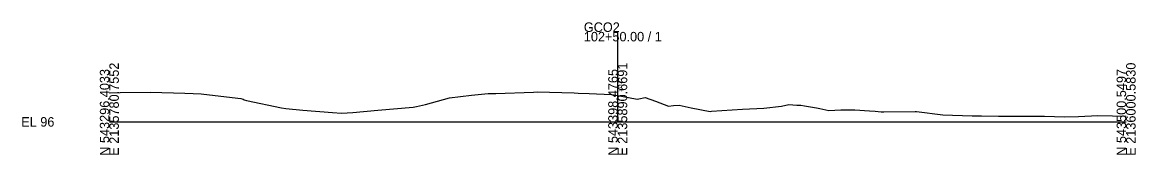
# Model space of a CAD drawing. Extents: x -14327 to 8886, y -10 to 39048.
# Drawn here: x 3974.3 to 4302.8, y 24990.3 to 25029.4 of the extents above; entities that cross this region are included whole.
import ezdxf

# ---------------------------------------------------------------- set-up
doc = ezdxf.new("R2010")
doc.units = 0
for name, color, linetype in [('RD_GPK_XS_Cell', 7, 'Continuous'), ('RD_XS_ExGround', 7, 'Continuous'), ('RD_XS_TX_Elev_EX', 7, 'Continuous')]:
    doc.layers.add(name, color=color, linetype=linetype)

msp = doc.modelspace()

# ---------------------------------------------------------------- linework, layer by layer
at = {"layer": 'RD_GPK_XS_Cell'}
for p, q in [((4150, 25000), (4150, 25026.55)), ((4000, 25000), (4150, 25000)), ((4150, 25000), (4300, 25000))]:
    msp.add_line(p, q, dxfattribs=at)
at = {"layer": 'RD_XS_ExGround'}
for p, q in [((4000, 25008.57), (4000.22, 25008.58)), ((4000.22, 25008.58), (4003.21, 25008.64)), ((4003.21, 25008.64), (4012.16, 25008.8)), ((4012.16, 25008.8), (4022.28, 25008.49)), ((4022.28, 25008.49), (4024.75, 25008.41)), ((4024.75, 25008.41), (4027.09, 25008.3)), ((4027.09, 25008.3), (4027.83, 25008.2)), ((4027.83, 25008.2), (4038.78, 25006.88)), ((4106.81, 25007.88), (4111.73, 25008.36)), ((4111.73, 25008.36), (4112.85, 25008.39)), ((4112.85, 25008.39), (4114.02, 25008.42)), ((4114.02, 25008.42), (4125.1, 25008.81)), ((4125.1, 25008.81), (4126.25, 25008.85)), ((4126.25, 25008.85), (4137.16, 25008.55)), ((4137.16, 25008.55), (4138.33, 25008.51)), ((4138.33, 25008.51), (4141.61, 25008.39)), ((4141.61, 25008.39), (4148.2, 25008.11)), ((4148.2, 25008.11), (4150, 25007.77)), ((4038.78, 25006.88), (4039.45, 25006.68)), ((4039.45, 25006.68), (4039.81, 25006.52)), ((4039.81, 25006.52), (4040.45, 25006.29)), ((4040.45, 25006.29), (4050.84, 25004.18)), ((4090.59, 25004.54), (4091.53, 25004.78)), ((4091.53, 25004.78), (4093.33, 25005.13)), ((4093.33, 25005.13), (4100.33, 25007.07)), ((4100.33, 25007.07), (4106.81, 25007.88)), ((4150, 25007.77), (4155.24, 25006.8)), ((4155.24, 25006.8), (4155.77, 25006.69)), ((4155.77, 25006.69), (4156.26, 25006.8)), ((4156.26, 25006.8), (4158.13, 25007.23)), ((4158.13, 25007.23), (4161.14, 25006.08)), ((4161.14, 25006.08), (4165.02, 25004.66)), ((4165.02, 25004.66), (4166.46, 25004.8)), ((4166.46, 25004.8), (4168.13, 25004.89)), ((4168.13, 25004.89), (4171.68, 25004.18)), ((4193.07, 25004.01), (4198.3, 25004.64)), ((4198.3, 25004.64), (4200.44, 25005.1)), ((4200.44, 25005.1), (4202.81, 25004.93)), ((4202.81, 25004.93), (4204.01, 25004.9)), ((4204.01, 25004.9), (4205.06, 25004.73)), ((4205.06, 25004.73), (4208.69, 25004.17)), ((4050.84, 25004.18), (4052.07, 25003.95)), ((4052.07, 25003.95), (4057.1, 25003.49)), ((4057.1, 25003.49), (4065.8, 25002.76)), ((4065.8, 25002.76), (4068.52, 25002.59)), ((4068.52, 25002.59), (4071.81, 25002.8)), ((4071.81, 25002.8), (4079.17, 25003.46)), ((4079.17, 25003.46), (4089.66, 25004.35)), ((4089.66, 25004.35), (4090.59, 25004.54)), ((4171.68, 25004.18), (4177.26, 25003.07)), ((4177.26, 25003.07), (4177.69, 25003.15)), ((4177.69, 25003.15), (4186.82, 25003.71)), ((4186.82, 25003.71), (4193.07, 25004.01)), ((4208.69, 25004.17), (4209.67, 25003.97)), ((4209.67, 25003.97), (4212.31, 25003.4)), ((4212.31, 25003.4), (4215.82, 25003.55)), ((4215.82, 25003.55), (4219.95, 25003.56)), ((4219.95, 25003.56), (4224.28, 25003.25)), ((4224.28, 25003.25), (4225.92, 25003.12)), ((4225.92, 25003.12), (4227.7, 25002.95)), ((4227.7, 25002.95), (4228.52, 25002.95)), ((4228.52, 25002.95), (4237.76, 25003.1)), ((4237.76, 25003.1), (4238.2, 25003.06)), ((4238.2, 25003.06), (4245.94, 25002.07)), ((4245.94, 25002.07), (4254.55, 25001.78)), ((4254.55, 25001.78), (4255.94, 25001.81)), ((4255.94, 25001.81), (4257.38, 25001.75)), ((4257.38, 25001.75), (4262.33, 25001.73)), ((4262.33, 25001.73), (4275.96, 25001.64)), ((4275.96, 25001.64), (4281.78, 25001.49)), ((4281.78, 25001.49), (4285.96, 25001.55)), ((4285.96, 25001.55), (4291.64, 25001.85)), ((4291.64, 25001.85), (4295.97, 25001.78)), ((4295.97, 25001.78), (4300, 25001.67))]:
    msp.add_line(p, q, dxfattribs=at)

# ---------------------------------------------------------------- texts
at = {"layer": 'RD_GPK_XS_Cell'}
for s, p in [('GCO2', (4140, 25026.55)), ('102+50.00 / 1', (4140, 25023.75)), ('EL 96', (3974, 24998.6))]:
    msp.add_text(s, height=2.8, dxfattribs=at).set_placement(p)
for s, p in [('N 543296.4033', (4000, 24990)), ('E 2135780.7552', (4002.8, 24990)), ('N 543398.4765', (4150, 24990)), ('E 2135890.6691', (4152.8, 24990)), ('N 543500.5497', (4300, 24990)), ('E 2136000.5830', (4302.8, 24990))]:
    msp.add_text(s, height=2.8, rotation=90, dxfattribs=at).set_placement(p)
at = {"layer": 'RD_XS_TX_Elev_EX'}
msp.add_text('103.77', height=1, rotation=90, dxfattribs=at).set_placement((4151.25, 25008.77))

doc.saveas('drawing.dxf')
